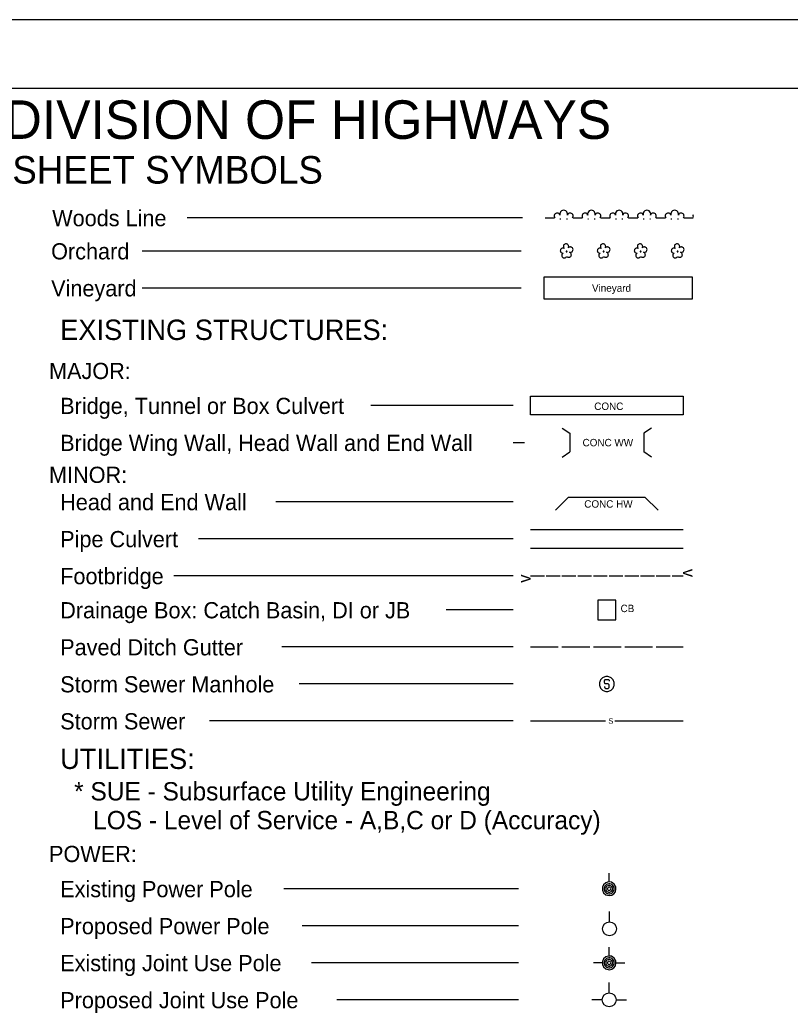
# Model space of a CAD drawing. Extents: x -0.53 to 3.34, y -0.27 to 4.33.
# Drawn here: x 1.661 to 2.361, y 3.426 to 4.328 of the extents above; entities that cross this region are included whole.
import ezdxf

# ---------------------------------------------------------------- set-up
doc = ezdxf.new("R2010")
doc.units = 0
for name, color, linetype in [('Sheet_Plan', 7, 'Continuous'), ('Sheet_Symbology', 7, 'Continuous'), ('z - Construction', 7, 'Continuous')]:
    doc.layers.add(name, color=color, linetype=linetype)

msp = doc.modelspace()

# ---------------------------------------------------------------- linework, layer by layer
at = {"layer": 'Sheet_Plan'}
msp.add_line((2.98823, 4.26594), (0.2799, 4.26594), dxfattribs=at)
at = {"layer": 'Sheet_Symbology'}
for p, q in [((2.11736, 4.14855), (1.81278, 4.14855)), ((2.13819, 4.14855), (2.1466, 4.14855)), ((2.15156, 4.14771), (2.1524, 4.14771)), ((2.15745, 4.14771), (2.15829, 4.14771)), ((2.16342, 4.14855), (2.17183, 4.14855)), ((2.17679, 4.14771), (2.17763, 4.14771)), ((2.18267, 4.14771), (2.18351, 4.14771)), ((2.18864, 4.14855), (2.19705, 4.14855)), ((2.20201, 4.14771), (2.20285, 4.14771)), ((2.2079, 4.14771), (2.20874, 4.14771)), ((2.21386, 4.14855), (2.22227, 4.14855)), ((2.22723, 4.14771), (2.22807, 4.14771)), ((2.23312, 4.14771), (2.23396, 4.14771)), ((2.23909, 4.14855), (2.2475, 4.14855)), ((2.25246, 4.14771), (2.2533, 4.14771)), ((2.25834, 4.14771), (2.25918, 4.14771)), ((2.26431, 4.14855), (2.27272, 4.14855)), ((2.11641, 4.1184), (1.77179, 4.1184)), ((2.11641, 4.08477), (1.77179, 4.08477)), ((2.10915, 3.97798), (1.97972, 3.97798)), ((2.15363, 3.95757), (2.16052, 3.95276)), ((2.23468, 3.95757), (2.22778, 3.95276)), ((2.10915, 3.94435), (2.11922, 3.94435)), ((2.16052, 3.95276), (2.16052, 3.93594)), ((2.22778, 3.95276), (2.22778, 3.93594)), ((2.15363, 3.93113), (2.16052, 3.93594)), ((2.23468, 3.93113), (2.22778, 3.93594)), ((2.10915, 3.89055), (1.8934, 3.89055)), ((2.14757, 3.88286), (2.15947, 3.89475)), ((2.15947, 3.89475), (2.22883, 3.89475)), ((2.22883, 3.89475), (2.24073, 3.88286)), ((2.12479, 3.86533), (2.26352, 3.86533)), ((2.10915, 3.85692), (1.82297, 3.85692)), ((2.12479, 3.84851), (2.26352, 3.84851)), ((2.10915, 3.82329), (1.80062, 3.82329)), ((2.12479, 3.82329), (2.1374, 3.82329)), ((2.13908, 3.82329), (2.15169, 3.82329)), ((2.15337, 3.82329), (2.16599, 3.82329)), ((2.16767, 3.82329), (2.18028, 3.82329)), ((2.18196, 3.82329), (2.19457, 3.82329)), ((2.19625, 3.82329), (2.20886, 3.82329)), ((2.21055, 3.82329), (2.22316, 3.82329)), ((2.22484, 3.82329), (2.23745, 3.82329)), ((2.23913, 3.82329), (2.25174, 3.82329)), ((2.25343, 3.82329), (2.26352, 3.82329)), ((2.10915, 3.79229), (2.04812, 3.79229)), ((2.10915, 3.75865), (1.89864, 3.75865)), ((2.12479, 3.75865), (2.15001, 3.75865)), ((2.15337, 3.75865), (2.1786, 3.75865)), ((2.18196, 3.75865), (2.20718, 3.75865)), ((2.21055, 3.75865), (2.23577, 3.75865)), ((2.23913, 3.75865), (2.26352, 3.75865)), ((2.19213, 3.72622), (2.19213, 3.72803)), ((2.19333, 3.72923), (2.19514, 3.72923)), ((2.19628, 3.72803), (2.19628, 3.72743)), ((2.10915, 3.72502), (1.91463, 3.72502)), ((2.19213, 3.72267), (2.19213, 3.72207)), ((2.19514, 3.72508), (2.19333, 3.72508)), ((2.19333, 3.72093), (2.19514, 3.72093)), ((2.19628, 3.72207), (2.19628, 3.72393)), ((2.10915, 3.69139), (1.83304, 3.69139)), ((2.12479, 3.69139), (2.19293, 3.69139)), ((2.20134, 3.69139), (2.26352, 3.69139)), ((2.19625, 3.54511), (2.19625, 3.55318)), ((2.11384, 3.53891), (1.9005, 3.53891)), ((2.19661, 3.50883), (2.19661, 3.51829)), ((2.11384, 3.50527), (1.91712, 3.50527)), ((2.19625, 3.47785), (2.19625, 3.48592)), ((2.11384, 3.47164), (1.92565, 3.47164)), ((2.19005, 3.47164), (2.18198, 3.47164)), ((2.20246, 3.47164), (2.21053, 3.47164)), ((2.19625, 3.44434), (2.19625, 3.4538)), ((2.11384, 3.43801), (1.94866, 3.43801)), ((2.18995, 3.43803), (2.18049, 3.43803)), ((2.20256, 3.43803), (2.21202, 3.43803))]:
    msp.add_line(p, q, dxfattribs=at)
for points in [[(2.15919, 4.12135), (2.15944, 4.12185), (2.15952, 4.12235), (2.15944, 4.12286), (2.15936, 4.12336), (2.1591, 4.12378), (2.15885, 4.1242), (2.15843, 4.12454), (2.15801, 4.12479), (2.15742, 4.12496), (2.157, 4.12496), (2.1565, 4.12488), (2.15599, 4.12471), (2.15557, 4.12446), (2.15515, 4.12412), (2.1549, 4.12362), (2.15473, 4.1232), (2.15465, 4.12269), (2.15465, 4.12219), (2.15473, 4.12168), (2.15498, 4.12126), (2.15532, 4.12076), (2.1549, 4.12101), (2.1544, 4.12109), (2.15389, 4.12109), (2.15347, 4.12093), (2.15305, 4.12076), (2.15263, 4.12042), (2.15229, 4.12008), (2.15204, 4.11966), (2.15196, 4.11924), (2.15187, 4.11866), (2.15196, 4.11824), (2.15213, 4.11781), (2.15246, 4.11739), (2.15271, 4.11706), (2.15313, 4.11681), (2.15364, 4.11655), (2.15406, 4.11647), (2.15456, 4.11647), (2.15414, 4.1163), (2.15372, 4.11596), (2.15347, 4.11563), (2.1533, 4.11512), (2.15313, 4.11462), (2.15313, 4.1142), (2.15322, 4.11369), (2.15347, 4.11327), (2.15372, 4.11285), (2.15406, 4.11252), (2.15448, 4.11227), (2.1549, 4.1121), (2.1554, 4.1121), (2.15591, 4.1121), (2.15633, 4.11218), (2.15675, 4.11252), (2.15717, 4.11277), (2.15759, 4.11353)], [(2.19282, 4.12135), (2.19307, 4.12185), (2.19316, 4.12235), (2.19307, 4.12286), (2.19299, 4.12336), (2.19274, 4.12378), (2.19248, 4.1242), (2.19206, 4.12454), (2.19164, 4.12479), (2.19105, 4.12496), (2.19063, 4.12496), (2.19013, 4.12488), (2.18962, 4.12471), (2.1892, 4.12446), (2.18878, 4.12412), (2.18853, 4.12362), (2.18836, 4.1232), (2.18828, 4.12269), (2.18828, 4.12219), (2.18836, 4.12168), (2.18862, 4.12126), (2.18895, 4.12076), (2.18853, 4.12101), (2.18803, 4.12109), (2.18752, 4.12109), (2.1871, 4.12093), (2.18668, 4.12076), (2.18626, 4.12042), (2.18593, 4.12008), (2.18567, 4.11966), (2.18559, 4.11924), (2.1855, 4.11866), (2.18559, 4.11824), (2.18576, 4.11781), (2.18609, 4.11739), (2.18635, 4.11706), (2.18677, 4.11681), (2.18727, 4.11655), (2.18769, 4.11647), (2.1882, 4.11647), (2.18777, 4.1163), (2.18735, 4.11596), (2.1871, 4.11563), (2.18693, 4.11512), (2.18677, 4.11462), (2.18677, 4.1142), (2.18685, 4.11369), (2.1871, 4.11327), (2.18735, 4.11285), (2.18769, 4.11252), (2.18811, 4.11227), (2.18853, 4.1121), (2.18904, 4.1121), (2.18954, 4.1121), (2.18996, 4.11218), (2.19038, 4.11252), (2.1908, 4.11277), (2.19122, 4.11353)], [(2.22645, 4.12135), (2.2267, 4.12185), (2.22679, 4.12235), (2.2267, 4.12286), (2.22662, 4.12336), (2.22637, 4.12378), (2.22611, 4.1242), (2.22569, 4.12454), (2.22527, 4.12479), (2.22469, 4.12496), (2.22426, 4.12496), (2.22376, 4.12488), (2.22326, 4.12471), (2.22284, 4.12446), (2.22242, 4.12412), (2.22216, 4.12362), (2.22199, 4.1232), (2.22191, 4.12269), (2.22191, 4.12219), (2.22199, 4.12168), (2.22225, 4.12126), (2.22258, 4.12076), (2.22216, 4.12101), (2.22166, 4.12109), (2.22115, 4.12109), (2.22073, 4.12093), (2.22031, 4.12076), (2.21989, 4.12042), (2.21956, 4.12008), (2.2193, 4.11966), (2.21922, 4.11924), (2.21914, 4.11866), (2.21922, 4.11824), (2.21939, 4.11781), (2.21972, 4.11739), (2.21998, 4.11706), (2.2204, 4.11681), (2.2209, 4.11655), (2.22132, 4.11647), (2.22183, 4.11647), (2.22141, 4.1163), (2.22099, 4.11596), (2.22073, 4.11563), (2.22057, 4.11512), (2.2204, 4.11462), (2.2204, 4.1142), (2.22048, 4.11369), (2.22073, 4.11327), (2.22099, 4.11285), (2.22132, 4.11252), (2.22174, 4.11227), (2.22216, 4.1121), (2.22267, 4.1121), (2.22317, 4.1121), (2.22359, 4.11218), (2.22401, 4.11252), (2.22443, 4.11277), (2.22485, 4.11353)], [(2.26008, 4.12135), (2.26033, 4.12185), (2.26042, 4.12235), (2.26033, 4.12286), (2.26025, 4.12336), (2.26, 4.12378), (2.25975, 4.1242), (2.25933, 4.12454), (2.25891, 4.12479), (2.25832, 4.12496), (2.2579, 4.12496), (2.25739, 4.12488), (2.25689, 4.12471), (2.25647, 4.12446), (2.25605, 4.12412), (2.25579, 4.12362), (2.25563, 4.1232), (2.25554, 4.12269), (2.25554, 4.12219), (2.25563, 4.12168), (2.25588, 4.12126), (2.25621, 4.12076), (2.25579, 4.12101), (2.25529, 4.12109), (2.25479, 4.12109), (2.25436, 4.12093), (2.25394, 4.12076), (2.25352, 4.12042), (2.25319, 4.12008), (2.25294, 4.11966), (2.25285, 4.11924), (2.25277, 4.11866), (2.25285, 4.11824), (2.25302, 4.11781), (2.25336, 4.11739), (2.25361, 4.11706), (2.25403, 4.11681), (2.25453, 4.11655), (2.25495, 4.11647), (2.25546, 4.11647), (2.25504, 4.1163), (2.25462, 4.11596), (2.25436, 4.11563), (2.2542, 4.11512), (2.25403, 4.11462), (2.25403, 4.1142), (2.25411, 4.11369), (2.25436, 4.11327), (2.25462, 4.11285), (2.25495, 4.11252), (2.25537, 4.11227), (2.25579, 4.1121), (2.2563, 4.1121), (2.2568, 4.1121), (2.25722, 4.11218), (2.25764, 4.11252), (2.25806, 4.11277), (2.25848, 4.11353)], [(2.15776, 4.1184), (2.15751, 4.1184), (2.15734, 4.11832), (2.15717, 4.11824), (2.15717, 4.11798), (2.15717, 4.11781), (2.15734, 4.11765), (2.15759, 4.11765), (2.15776, 4.11765), (2.15793, 4.11781), (2.15801, 4.11807), (2.15793, 4.11824), (2.15776, 4.1184)], [(2.15759, 4.11353), (2.1586, 4.11294), (2.1591, 4.11277), (2.15961, 4.11269), (2.16011, 4.11277), (2.16053, 4.11294), (2.16095, 4.11319), (2.16137, 4.11353), (2.16163, 4.11395), (2.16179, 4.11437), (2.16196, 4.11487), (2.16188, 4.11538), (2.16179, 4.11588), (2.16146, 4.11639), (2.16121, 4.11672), (2.16079, 4.11697), (2.16028, 4.11723), (2.16079, 4.11714), (2.16137, 4.11714), (2.16179, 4.11731), (2.1623, 4.11756), (2.16272, 4.11781), (2.16306, 4.11824), (2.16331, 4.11874), (2.16339, 4.11924), (2.16348, 4.11975), (2.16339, 4.12025), (2.16322, 4.12076), (2.16289, 4.12118), (2.16247, 4.1216), (2.16205, 4.12185), (2.16154, 4.12202), (2.16104, 4.1221), (2.16053, 4.1221), (2.16003, 4.12193), (2.15961, 4.12168), (2.15919, 4.12135)], [(2.19139, 4.1184), (2.19114, 4.1184), (2.19097, 4.11832), (2.1908, 4.11824), (2.1908, 4.11798), (2.1908, 4.11781), (2.19097, 4.11765), (2.19122, 4.11765), (2.19139, 4.11765), (2.19156, 4.11781), (2.19164, 4.11807), (2.19156, 4.11824), (2.19139, 4.1184)], [(2.19122, 4.11353), (2.19223, 4.11294), (2.19274, 4.11277), (2.19324, 4.11269), (2.19374, 4.11277), (2.19416, 4.11294), (2.19459, 4.11319), (2.19501, 4.11353), (2.19526, 4.11395), (2.19543, 4.11437), (2.19559, 4.11487), (2.19551, 4.11538), (2.19543, 4.11588), (2.19509, 4.11639), (2.19484, 4.11672), (2.19442, 4.11697), (2.19391, 4.11723), (2.19442, 4.11714), (2.19501, 4.11714), (2.19543, 4.11731), (2.19593, 4.11756), (2.19635, 4.11781), (2.19669, 4.11824), (2.19694, 4.11874), (2.19702, 4.11924), (2.19711, 4.11975), (2.19702, 4.12025), (2.19686, 4.12076), (2.19652, 4.12118), (2.1961, 4.1216), (2.19568, 4.12185), (2.19517, 4.12202), (2.19467, 4.1221), (2.19416, 4.1221), (2.19366, 4.12193), (2.19324, 4.12168), (2.19282, 4.12135)], [(2.22502, 4.1184), (2.22477, 4.1184), (2.2246, 4.11832), (2.22443, 4.11824), (2.22443, 4.11798), (2.22443, 4.11781), (2.2246, 4.11765), (2.22485, 4.11765), (2.22502, 4.11765), (2.22519, 4.11781), (2.22527, 4.11807), (2.22519, 4.11824), (2.22502, 4.1184)], [(2.22485, 4.11353), (2.22586, 4.11294), (2.22637, 4.11277), (2.22687, 4.11269), (2.22738, 4.11277), (2.2278, 4.11294), (2.22822, 4.11319), (2.22864, 4.11353), (2.22889, 4.11395), (2.22906, 4.11437), (2.22923, 4.11487), (2.22914, 4.11538), (2.22906, 4.11588), (2.22872, 4.11639), (2.22847, 4.11672), (2.22805, 4.11697), (2.22754, 4.11723), (2.22805, 4.11714), (2.22864, 4.11714), (2.22906, 4.11731), (2.22956, 4.11756), (2.22998, 4.11781), (2.23032, 4.11824), (2.23057, 4.11874), (2.23065, 4.11924), (2.23074, 4.11975), (2.23065, 4.12025), (2.23049, 4.12076), (2.23015, 4.12118), (2.22973, 4.1216), (2.22931, 4.12185), (2.22881, 4.12202), (2.2283, 4.1221), (2.2278, 4.1221), (2.22729, 4.12193), (2.22687, 4.12168), (2.22645, 4.12135)], [(2.25865, 4.1184), (2.2584, 4.1184), (2.25823, 4.11832), (2.25806, 4.11824), (2.25806, 4.11798), (2.25806, 4.11781), (2.25823, 4.11765), (2.25848, 4.11765), (2.25865, 4.11765), (2.25882, 4.11781), (2.25891, 4.11807), (2.25882, 4.11824), (2.25865, 4.1184)], [(2.25848, 4.11353), (2.25949, 4.11294), (2.26, 4.11277), (2.2605, 4.11269), (2.26101, 4.11277), (2.26143, 4.11294), (2.26185, 4.11319), (2.26227, 4.11353), (2.26252, 4.11395), (2.26269, 4.11437), (2.26286, 4.11487), (2.26277, 4.11538), (2.26269, 4.11588), (2.26235, 4.11639), (2.2621, 4.11672), (2.26168, 4.11697), (2.26118, 4.11723), (2.26168, 4.11714), (2.26227, 4.11714), (2.26269, 4.11731), (2.26319, 4.11756), (2.26361, 4.11781), (2.26395, 4.11824), (2.2642, 4.11874), (2.26429, 4.11924), (2.26437, 4.11975), (2.26429, 4.12025), (2.26412, 4.12076), (2.26378, 4.12118), (2.26336, 4.1216), (2.26294, 4.12185), (2.26244, 4.12202), (2.26193, 4.1221), (2.26143, 4.1221), (2.26092, 4.12193), (2.2605, 4.12168), (2.26008, 4.12135)], [(2.13724, 4.09486), (2.27177, 4.09486), (2.27177, 4.07468), (2.13724, 4.07468), (2.13724, 4.09486)], [(2.12479, 3.98639), (2.26352, 3.98639), (2.26352, 3.96958), (2.12479, 3.96958), (2.12479, 3.98639)], [(2.19415, 3.73185), (2.19328, 3.7318), (2.19246, 3.73163), (2.19164, 3.73136), (2.19087, 3.73098), (2.19016, 3.73054), (2.18951, 3.72999), (2.18891, 3.72934), (2.18842, 3.72868), (2.18798, 3.72792), (2.18771, 3.7271), (2.18749, 3.72628), (2.18738, 3.72546), (2.18738, 3.72459), (2.18749, 3.72377), (2.18771, 3.72289), (2.18798, 3.72213), (2.18842, 3.72136), (2.18891, 3.72071), (2.18951, 3.72005), (2.19016, 3.71951), (2.19087, 3.71907), (2.19164, 3.71869), (2.19246, 3.71841), (2.19333, 3.71825), (2.19415, 3.7182), (2.19503, 3.71825), (2.19584, 3.71841), (2.19666, 3.71869), (2.19743, 3.71907), (2.19814, 3.71951), (2.19879, 3.72005), (2.1994, 3.72071), (2.19989, 3.72136), (2.20032, 3.72213), (2.2006, 3.72295), (2.20082, 3.72377), (2.20092, 3.72459), (2.20092, 3.72546), (2.20082, 3.72628), (2.2006, 3.72715), (2.20032, 3.72792), (2.19989, 3.72868), (2.1994, 3.72934), (2.19879, 3.72999), (2.19814, 3.73054), (2.19743, 3.73098), (2.19666, 3.73136), (2.19584, 3.73163), (2.19497, 3.7318), (2.19415, 3.73185)], [(2.19213, 3.72803), (2.19224, 3.72841), (2.1924, 3.72874), (2.19262, 3.72896), (2.19295, 3.72912), (2.19333, 3.72923)], [(2.19514, 3.72923), (2.19546, 3.72912), (2.19579, 3.72896), (2.19606, 3.72874), (2.19623, 3.72841), (2.19628, 3.72803)], [(2.19333, 3.72508), (2.19295, 3.72513), (2.19262, 3.7253), (2.1924, 3.72557), (2.19224, 3.7259), (2.19213, 3.72622)], [(2.19213, 3.72213), (2.19224, 3.72175), (2.1924, 3.72142), (2.19262, 3.72115), (2.19295, 3.72098), (2.19333, 3.72093)], [(2.19628, 3.72388), (2.19623, 3.72426), (2.19606, 3.72459), (2.19579, 3.72486), (2.19546, 3.72502), (2.19514, 3.72508)], [(2.19514, 3.72093), (2.19546, 3.72098), (2.19579, 3.72115), (2.19606, 3.72142), (2.19623, 3.72175), (2.19628, 3.72213)], [(2.20085, 3.53891), (2.20072, 3.54002), (2.20035, 3.54101), (2.19973, 3.54188), (2.19898, 3.54263), (2.19812, 3.54313), (2.197, 3.54337), (2.196, 3.5435), (2.19489, 3.54325), (2.19389, 3.54288), (2.19315, 3.54226), (2.19241, 3.54139), (2.19191, 3.54052), (2.19166, 3.5394), (2.19166, 3.53841), (2.19191, 3.53729), (2.19241, 3.53642), (2.19315, 3.53555), (2.19389, 3.53493), (2.19489, 3.53456), (2.196, 3.53431), (2.197, 3.53444), (2.19812, 3.53468), (2.19898, 3.53518), (2.19973, 3.53593), (2.20035, 3.5368), (2.20072, 3.53779), (2.20085, 3.53891)], [(2.19936, 3.53891), (2.19923, 3.53978), (2.19886, 3.54064), (2.19824, 3.54126), (2.1975, 3.54176), (2.19675, 3.54201), (2.19576, 3.54201), (2.19501, 3.54176), (2.19427, 3.54126), (2.19365, 3.54064), (2.19327, 3.53978), (2.19315, 3.53891), (2.19327, 3.53804), (2.19365, 3.53717), (2.19427, 3.53655), (2.19501, 3.53605), (2.19576, 3.5358), (2.19675, 3.5358), (2.1975, 3.53605), (2.19824, 3.53655), (2.19886, 3.53717), (2.19923, 3.53804), (2.19936, 3.53891)], [(2.19774, 3.53891), (2.19762, 3.53953), (2.19725, 3.54002), (2.19675, 3.54027), (2.19613, 3.5404), (2.19551, 3.54015), (2.19501, 3.53978), (2.19476, 3.53916), (2.19476, 3.53866), (2.19501, 3.53804), (2.19551, 3.53766), (2.19613, 3.53742), (2.19675, 3.53754), (2.19725, 3.53779), (2.19762, 3.53829), (2.19774, 3.53891)], [(2.20085, 3.47164), (2.20072, 3.47276), (2.20035, 3.47375), (2.19973, 3.47462), (2.19898, 3.47536), (2.19812, 3.47587), (2.197, 3.47611), (2.196, 3.47624), (2.19489, 3.47599), (2.19389, 3.47562), (2.19315, 3.475), (2.19241, 3.47413), (2.19191, 3.47326), (2.19166, 3.47214), (2.19166, 3.47115), (2.19191, 3.47003), (2.19241, 3.46916), (2.19315, 3.46829), (2.19389, 3.46767), (2.19489, 3.4673), (2.196, 3.46705), (2.197, 3.46717), (2.19812, 3.46742), (2.19898, 3.46792), (2.19973, 3.46866), (2.20035, 3.46953), (2.20072, 3.47053), (2.20085, 3.47164)], [(2.19936, 3.47164), (2.19923, 3.47251), (2.19886, 3.47338), (2.19824, 3.474), (2.1975, 3.4745), (2.19675, 3.47475), (2.19576, 3.47475), (2.19501, 3.4745), (2.19427, 3.474), (2.19365, 3.47338), (2.19327, 3.47251), (2.19315, 3.47164), (2.19327, 3.47077), (2.19365, 3.46991), (2.19427, 3.46928), (2.19501, 3.46879), (2.19576, 3.46854), (2.19675, 3.46854), (2.1975, 3.46879), (2.19824, 3.46928), (2.19886, 3.46991), (2.19923, 3.47077), (2.19936, 3.47164)], [(2.19774, 3.47164), (2.19762, 3.47226), (2.19725, 3.47276), (2.19675, 3.47301), (2.19613, 3.47313), (2.19551, 3.47289), (2.19501, 3.47251), (2.19476, 3.47189), (2.19476, 3.47139), (2.19501, 3.47077), (2.19551, 3.4704), (2.19613, 3.47015), (2.19675, 3.47028), (2.19725, 3.47053), (2.19762, 3.47102), (2.19774, 3.47164)]]:
    msp.add_lwpolyline(points, dxfattribs=at)
for points in [[(2.18606, 3.78335), (2.20222, 3.78335), (2.20222, 3.80124), (2.18606, 3.80124)], [(2.19625, 3.5327), (2.19886, 3.53319), (2.2006, 3.53444), (2.20196, 3.53618), (2.20246, 3.53853), (2.20221, 3.54077), (2.20097, 3.543), (2.19849, 3.54486), (2.19563, 3.54511), (2.19315, 3.54437), (2.19117, 3.54263), (2.19017, 3.54027), (2.19017, 3.53754), (2.19117, 3.53518), (2.1934, 3.53332)], [(2.19625, 3.46543), (2.19886, 3.46593), (2.2006, 3.46717), (2.20196, 3.46891), (2.20246, 3.47127), (2.20221, 3.47351), (2.20097, 3.47574), (2.19849, 3.4776), (2.19563, 3.47785), (2.19315, 3.4771), (2.19117, 3.47536), (2.19017, 3.47301), (2.19017, 3.47028), (2.19117, 3.46792), (2.1934, 3.46605)]]:
    msp.add_lwpolyline(points, close=True, dxfattribs=at)
for centre in [(2.19661, 3.50252), (2.19625, 3.43801)]:
    msp.add_circle(centre, 0.00631, dxfattribs=at)
for centre, radius, start, end in [((2.14904, 4.15026), 0.00266, 18.43495, 219.23152), ((2.15493, 4.15194), 0.00347, 345.96376, 194.03624), ((2.16081, 4.15026), 0.00266, 320.76848, 161.56505), ((2.17426, 4.15026), 0.00266, 18.43495, 219.23152), ((2.18014, 4.15194), 0.00347, 345.96376, 194.03624), ((2.18603, 4.15026), 0.00266, 320.76848, 161.56505), ((2.19948, 4.15026), 0.00266, 18.43495, 219.23152), ((2.20537, 4.15194), 0.00347, 345.96376, 194.03624), ((2.21125, 4.15026), 0.00266, 320.76848, 161.56505), ((2.22471, 4.15026), 0.00266, 18.43495, 219.23152), ((2.23059, 4.15194), 0.00347, 345.96376, 194.03624), ((2.23648, 4.15026), 0.00266, 320.76848, 161.56505), ((2.24993, 4.15026), 0.00266, 18.43495, 219.23152), ((2.25582, 4.15194), 0.00347, 345.96376, 194.03624), ((2.2617, 4.15026), 0.00266, 320.76848, 161.56505), ((2.27515, 4.15026), 0.00266, 156.25102, 203.74899)]:
    msp.add_arc(centre, radius, start, end, dxfattribs=at)
at = {"layer": 'z - Construction'}
msp.add_line((3.05073, 4.32844), (0.2174, 4.32844), dxfattribs=at)

# ---------------------------------------------------------------- texts
at = {"layer": 'Sheet_Symbology'}
for s, height, p in [('STATE OF NORTH CAROLINA, DIVISION OF HIGHWAYS', 0.035, (0.9603, 4.2203)), ('CONVENTIONAL  PLAN SHEET SYMBOLS', 0.025, (1.27472, 4.17969)), ('Woods Line', 0.014714, (1.68997, 4.14094)), ('Orchard', 0.014714, (1.68901, 4.11079)), ('Vineyard', 0.014714, (1.68901, 4.07716)), ('EXISTING STRUCTURES:', 0.0184972, (1.69723, 4.03759)), ('MAJOR:', 0.014714, (1.6871, 4.00209)), ('Bridge, Tunnel or Box Culvert', 0.0147137, (1.69723, 3.97033)), ('CONC', 0.006726, (2.1827, 3.97401)), ('Bridge Wing Wall, Head Wall and End Wall', 0.0147137, (1.69723, 3.9367)), ('MINOR:', 0.014714, (1.6871, 3.90771)), ('Head and End Wall', 0.0147137, (1.69723, 3.8829)), ('CONC HW', 0.006726, (2.17364, 3.88523)), ('Pipe Culvert', 0.0147137, (1.69723, 3.84929)), ('Footbridge', 0.014714, (1.69725, 3.81566)), ('Drainage Box: Catch Basin, DI or JB', 0.0147137, (1.69725, 3.78466)), ('CB', 0.006726, (2.20666, 3.79031)), ('Paved Ditch Gutter', 0.0147137, (1.69725, 3.751)), ('Storm Sewer Manhole', 0.0147137, (1.69725, 3.71737)), ('Storm Sewer', 0.0147137, (1.69725, 3.68374)), ('S', 0.00504, (2.19562, 3.68887)), ('UTILITIES:', 0.018497, (1.69723, 3.64781)), ('* SUE - Subsurface Utility Engineering', 0.0166475, (1.7099, 3.61919)), ('LOS - Level of Service - A,B,C or D (Accuracy) ', 0.0166475, (1.72716, 3.59301)), ('POWER:', 0.014714, (1.6871, 3.56322)), ('Existing Power Pole', 0.0147137, (1.69725, 3.53128)), ('Proposed Power Pole', 0.0147137, (1.69725, 3.49764)), ('Existing Joint Use Pole', 0.0147137, (1.69725, 3.46403)), ('Proposed Joint Use Pole', 0.0147137, (1.69727, 3.43038))]:
    msp.add_text(s, height=height, dxfattribs=at).set_placement(p)
for s, height, rotation, p in [('Vineyard', 0.006726, 0.00002, (2.18067, 4.08141)), ('CONC WW', 0.006726, 0.00002, (2.17208, 3.94099)), ('v', 0.0111, 270.24085, (2.26349, 3.82957)), ('v', 0.0111, 89.75915, (2.12477, 3.817))]:
    msp.add_text(s, height=height, rotation=rotation, dxfattribs=at).set_placement(p)

doc.saveas('drawing.dxf')
